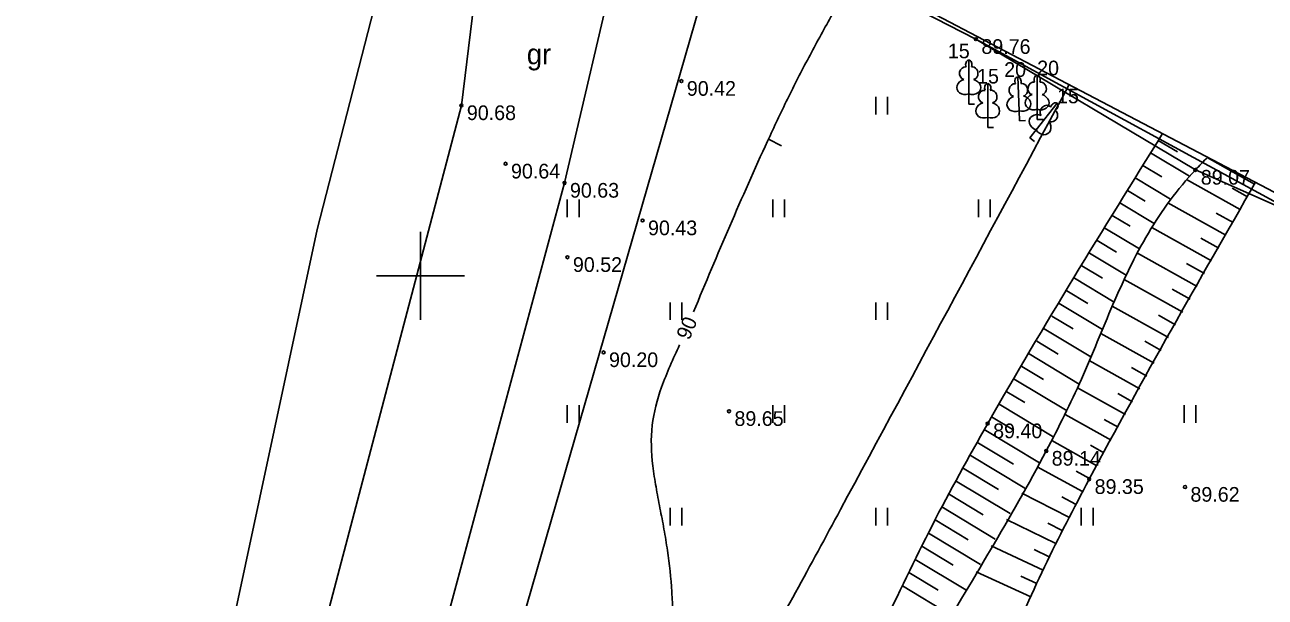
# Model space of a CAD drawing. Extents: x 635228 to 635525, y 248590 to 248800.
# Drawn here: x 635336.53 to 635378.76, y 248739.05 to 248758.56 of the extents above; entities that cross this region are included whole.
import ezdxf

# ---------------------------------------------------------------- set-up
doc = ezdxf.new("R2010")
doc.units = 0
for name, color, linetype in [('CELI_CMAL_####_####_#', 7, 'Continuous'), ('CELI_CSEG_####_TKST_#', 7, 'Continuous'), ('GEOD_ELEM_####_####_#', 7, 'Continuous'), ('NORB_ZOGS_ZSTP_####_#', 7, 'Continuous'), ('RAMI_UZMR_####_####_#', 7, 'Continuous'), ('RELJ_AATZ_####_TKST_#', 7, 'Continuous'), ('RELJ_ELEM_####_####_#', 7, 'Continuous'), ('RELJ_HORZ_####_TKST_#', 7, 'Continuous'), ('RELJ_HORZ_PAMT_####_#', 7, 'Continuous'), ('RELJ_HORZ_RESN_####_#', 7, 'Continuous'), ('RELJ_NOGA_####_####_#', 7, 'Continuous'), ('RELJ_NOGL_####_####_#', 7, 'Continuous'), ('ROBZ_IERR_####_####_#', 7, 'Continuous'), ('ROBZ_PROJ_####_####_#', 7, 'Continuous'), ('ROBZ_UZMR_####_####_#', 7, 'Continuous'), ('TERT_DIAM_####_TKST_#', 7, 'Continuous'), ('TERT_ELEM_####_####_#', 7, 'Continuous')]:
    doc.layers.add(name, color=color, linetype=linetype)

msp = doc.modelspace()

# ---------------------------------------------------------------- linework, layer by layer
at = {"layer": 'CELI_CMAL_####_####_#'}
for points in [[(635327.703, 248680.035), (635336.747, 248691.797), (635341.71, 248705.602), (635344.776, 248717.251), (635350.856, 248738.106), (635354.904, 248753.168), (635356.755, 248761.086), (635356.988, 248762.081)], [(635352.126, 248761.775), (635351.394, 248755.812), (635346.791, 248738.298), (635340.529, 248716.56), (635338.144, 248706.864), (635332.779, 248692.762), (635327.977, 248685.285), (635325.201, 248682.696)]]:
    msp.add_lwpolyline(points, dxfattribs=at)
at = {"layer": 'GEOD_ELEM_####_####_#'}
for p, q in [((635350, 248751.5), (635350, 248750)), ((635348.5, 248750), (635350, 248750)), ((635350, 248750), (635350, 248748.5)), ((635350, 248750), (635351.5, 248750))]:
    msp.add_line(p, q, dxfattribs=at)
at = {"layer": 'NORB_ZOGS_ZSTP_####_#'}
msp.add_lwpolyline([(635360.648, 248762.312), (635368.914, 248758.068), (635380.222, 248751.913), (635388.377, 248747.789), (635390.826, 248746.16), (635396.286, 248743.485), (635409.766, 248736.46), (635417.87, 248732.3), (635426.003, 248728.155), (635436.69, 248722.584), (635450.108, 248715.457), (635458.287, 248711.346), (635460.113, 248714.625)], dxfattribs=at)
at = {"layer": 'RAMI_UZMR_####_####_#'}
for points in [[(635352.126, 248761.775), (635360.648, 248762.312), (635368.914, 248758.068), (635376.384, 248753.612), (635380.222, 248751.913)], [(635379.918, 248627.738), (635364.657, 248634.365), (635359.326, 248636.387), (635355.893, 248639.014), (635323.971, 248655.917), (635326.8, 248663.851), (635331.354, 248676.262), (635327.703, 248680.035), (635326.374, 248681.182), (635325.201, 248682.696), (635327.977, 248685.285), (635332.779, 248692.762), (635338.144, 248706.864), (635340.529, 248716.56), (635346.791, 248738.298), (635351.394, 248755.812), (635352.126, 248761.775)]]:
    msp.add_lwpolyline(points, dxfattribs=at)
at = {"layer": 'RELJ_ELEM_####_####_#'}
for centre in [(635368.914, 248758.068), (635358.884, 248756.64), (635351.394, 248755.812), (635352.897, 248753.822), (635376.384, 248753.612), (635354.904, 248753.168), (635357.563, 248751.889), (635355.005, 248750.638), (635355.005, 248750.637), (635356.235, 248747.395), (635360.506, 248745.39), (635369.314, 248744.971), (635371.307, 248744.035), (635372.769, 248743.072), (635376.032, 248742.807)]:
    msp.add_circle(centre, 0.05, dxfattribs=at)
at = {"layer": 'RELJ_HORZ_PAMT_####_#'}
msp.add_spline([(635330.297, 248677.354), (635331.177, 248678.319), (635332.06, 248679.489), (635332.793, 248680.772), (635333.481, 248682.089), (635334.226, 248683.36), (635335.284, 248684.77), (635336.431, 248686.125), (635337.538, 248687.508), (635338.035, 248688.237), (635338.472, 248689.004), (635339.583, 248691.554), (635340.487, 248694.188), (635341.335, 248696.84), (635341.787, 248698.153), (635342.281, 248699.447), (635343.206, 248701.423), (635344.222, 248703.369), (635345.157, 248705.345), (635345.54, 248706.364), (635345.837, 248707.412), (635346.445, 248710.352), (635346.944, 248713.307), (635347.835, 248719.233), (635348.116, 248721.113), (635348.378, 248722.995), (635348.645, 248724.878), (635348.937, 248726.758), (635349.503, 248728.159), (635350.332, 248729.539), (635351.235, 248730.852), (635351.672, 248731.412), (635352.153, 248731.934), (635352.67, 248732.415), (635353.216, 248732.849), (635353.585, 248732.808), (635353.973, 248732.393), (635354.375, 248731.871), (635354.581, 248731.654), (635354.79, 248731.511), (635355.514, 248731.162), (635356.357, 248730.815), (635357.156, 248730.69), (635357.748, 248731.008), (635358.207, 248731.666), (635358.657, 248732.33), (635359.531, 248733.675), (635361.193, 248736.42), (635362.771, 248739.216), (635364.301, 248742.038), (635372.089, 248756.526)], degree=3, dxfattribs=at)
at = {"layer": 'RELJ_HORZ_RESN_####_#'}
msp.add_line((635361.849, 248754.663), (635362.292, 248754.431), dxfattribs=at)
for points in [[(635364.86, 248760.318), (635364.781, 248760.19), (635364.373, 248759.513), (635363.977, 248758.829), (635363.593, 248758.138), (635363.219, 248757.441), (635362.497, 248756.029), (635361.819, 248754.597), (635360.53, 248751.697), (635359.299, 248748.781)], [(635358.825, 248747.654), (635358.21, 248746.207), (635357.892, 248744.91), (635357.912, 248743.531), (635358.021, 248742.809), (635358.155, 248742.09), (635358.292, 248741.37), (635358.408, 248740.649), (635358.559, 248739.236), (635358.591, 248738.526), (635358.581, 248737.819), (635358.196, 248736.504), (635357.825, 248735.885), (635357.587, 248735.587), (635357.454, 248735.441), (635357.311, 248735.297), (635356.977, 248735.19), (635356.617, 248735.341), (635356.249, 248735.549), (635356.069, 248735.611), (635355.895, 248735.612), (635355.014, 248735.429), (635354.125, 248735.201), (635352.879, 248734.574), (635352.692, 248734.418), (635352.512, 248734.242), (635351.714, 248733.154), (635351.096, 248732.023), (635349.587, 248729.373), (635348.887, 248728.028), (635348.565, 248727.339), (635348.268, 248726.636), (635347.624, 248724.653), (635347.206, 248722.617), (635346.842, 248719.134)]]:
    msp.add_spline(points, degree=3, dxfattribs=at)
at = {"layer": 'RELJ_NOGA_####_####_#'}
for p, q in [((635375.123, 248754.619), (635375.774, 248754.228)), ((635374.86, 248754.194), (635376.183, 248753.397)), ((635378.399, 248753.133), (635376.791, 248754.033)), ((635374.598, 248753.768), (635375.241, 248753.381)), ((635374.337, 248753.342), (635375.543, 248752.615)), ((635377.911, 248752.26), (635376.082, 248753.284)), ((635374.076, 248752.915), (635374.679, 248752.552)), ((635378.155, 248752.696), (635377.638, 248752.986)), ((635373.816, 248752.488), (635374.982, 248751.786)), ((635377.423, 248751.387), (635375.452, 248752.49)), ((635373.556, 248752.061), (635374.165, 248751.694)), ((635377.667, 248751.824), (635377.094, 248752.144)), ((635373.297, 248751.633), (635374.483, 248750.919)), ((635376.934, 248750.515), (635374.9, 248751.653)), ((635373.039, 248751.205), (635373.699, 248750.808)), ((635377.179, 248750.951), (635376.575, 248751.289)), ((635372.781, 248750.777), (635374.032, 248750.023)), ((635376.446, 248749.642), (635374.41, 248750.781)), ((635372.523, 248750.349), (635373.227, 248749.925)), ((635376.69, 248750.078), (635376.078, 248750.421)), ((635372.265, 248749.92), (635373.615, 248749.107)), ((635375.958, 248748.769), (635373.966, 248749.884)), ((635372.008, 248749.491), (635372.723, 248749.061)), ((635376.202, 248749.206), (635375.596, 248749.545)), ((635371.752, 248749.062), (635373.219, 248748.179)), ((635375.469, 248747.897), (635373.555, 248748.968)), ((635371.495, 248748.633), (635372.219, 248748.197)), ((635375.713, 248748.333), (635375.127, 248748.662)), ((635371.239, 248748.203), (635372.829, 248747.246)), ((635374.981, 248747.024), (635373.162, 248748.042)), ((635370.983, 248747.774), (635371.715, 248747.333)), ((635375.225, 248747.46), (635374.665, 248747.774)), ((635370.727, 248747.344), (635372.432, 248746.318)), ((635370.471, 248746.915), (635371.211, 248746.469)), ((635374.492, 248746.152), (635372.773, 248747.114)), ((635374.737, 248746.588), (635374.206, 248746.885)), ((635370.215, 248746.485), (635372.016, 248745.401)), ((635369.96, 248746.055), (635370.58, 248745.682)), ((635374.004, 248745.279), (635372.376, 248746.19)), ((635374.248, 248745.715), (635373.747, 248745.996)), ((635369.704, 248745.626), (635371.566, 248744.504)), ((635369.448, 248745.196), (635370.203, 248744.741)), ((635373.516, 248744.406), (635371.957, 248745.278)), ((635373.76, 248744.843), (635373.283, 248745.109)), ((635369.193, 248744.766), (635371.076, 248743.633)), ((635368.942, 248744.334), (635370.187, 248743.584)), ((635373.027, 248743.534), (635371.503, 248744.387)), ((635373.272, 248743.97), (635372.811, 248744.228)), ((635368.695, 248743.899), (635370.576, 248742.766)), ((635368.453, 248743.461), (635369.676, 248742.724)), ((635372.542, 248742.659), (635370.998, 248743.497)), ((635372.783, 248743.097), (635372.326, 248743.353)), ((635368.215, 248743.02), (635370.075, 248741.9)), ((635367.98, 248742.578), (635369.164, 248741.865)), ((635372.075, 248741.775), (635370.478, 248742.597)), ((635367.749, 248742.134), (635369.573, 248741.036)), ((635372.306, 248742.219), (635371.836, 248742.468)), ((635367.521, 248741.688), (635368.653, 248741.006)), ((635371.629, 248740.88), (635369.957, 248741.697)), ((635367.295, 248741.24), (635369.07, 248740.171)), ((635371.85, 248741.329), (635371.359, 248741.572)), ((635371.198, 248739.978), (635369.436, 248740.801)), ((635367.071, 248740.791), (635368.14, 248740.147)), ((635371.412, 248740.43), (635370.897, 248740.676)), ((635366.849, 248740.341), (635368.566, 248739.307)), ((635366.629, 248739.89), (635367.628, 248739.288)), ((635370.778, 248739.07), (635368.923, 248739.919)), ((635370.987, 248739.525), (635370.444, 248739.774)), ((635366.41, 248739.438), (635368.062, 248738.443))]:
    msp.add_line(p, q, dxfattribs=at)
for points in [[(635375.27, 248754.857), (635369.314, 248744.971), (635367.429, 248741.507), (635365.696, 248737.957), (635363.943, 248734.417), (635363.006, 248732.681), (635362, 248730.984), (635361.355, 248730.103), (635360.628, 248729.283), (635359.885, 248728.474), (635359.193, 248727.625), (635357.58, 248725.368), (635356.018, 248723.079), (635353.089, 248718.349), (635349.569, 248710.638), (635349.163, 248709.221), (635348.864, 248707.772), (635348.539, 248706.335), (635348.053, 248704.954), (635343.12, 248694.162), (635337.407, 248681.667), (635331.093, 248670.147), (635326.8, 248663.851)], [(635326.8, 248663.851), (635325.31, 248661.345), (635325.174, 248660.918), (635325.219, 248660.451), (635325.416, 248659.984), (635325.736, 248659.553), (635326.126, 248659.27), (635326.575, 248659.146), (635327.409, 248659.333), (635327.907, 248659.688), (635328.397, 248660.078), (635328.864, 248660.506), (635329.288, 248660.978), (635331.594, 248663.918), (635332.687, 248665.412), (635333.734, 248666.95), (635337.875, 248673.353), (635341.554, 248680.001), (635347.428, 248693.006), (635353.063, 248706.101), (635354.098, 248708.621), (635355.097, 248711.155), (635356.117, 248713.682), (635356.653, 248714.935), (635357.216, 248716.179), (635358.916, 248719.218), (635360.822, 248722.14), (635362.339, 248724.363), (635363.916, 248726.545), (635365.467, 248728.744), (635366.906, 248731.015), (635368.464, 248733.981), (635369.863, 248737.03), (635371.249, 248740.086), (635372.769, 248743.072), (635378.435, 248753.196)]]:
    msp.add_spline(points, degree=3, dxfattribs=at)
at = {"layer": 'RELJ_NOGL_####_####_#'}
msp.add_spline([(635326.936, 248660.713), (635331.766, 248667.928), (635333.88, 248671.254), (635335.853, 248674.668), (635337.706, 248678.153), (635339.464, 248681.691), (635342.12, 248687.391), (635344.65, 248693.14), (635347.108, 248698.916), (635349.548, 248704.698), (635350.777, 248707.84), (635351.91, 248711.022), (635353.067, 248714.195), (635353.692, 248715.764), (635354.368, 248717.312), (635355.034, 248718.536), (635355.835, 248719.677), (635357.677, 248721.811), (635359.567, 248723.919), (635361.176, 248726.206), (635362.355, 248728.434), (635362.939, 248729.551), (635363.546, 248730.656), (635367.422, 248737.348), (635371.307, 248744.035), (635372.506, 248746.487), (635373.579, 248749.023), (635374.785, 248751.459), (635376.384, 248753.612), (635376.807, 248754.05)], degree=3, dxfattribs=at)
at = {"layer": 'ROBZ_IERR_####_####_#'}
msp.add_lwpolyline([(635390.87, 248797.676), (635383.387, 248769.687), (635386.484, 248768.447), (635478.377, 248731.658), (635482.561, 248729.828), (635465.459, 248707.539), (635458.607, 248711.134), (635360.483, 248762.615), (635360.888, 248769.918), (635363.321, 248797.676)], dxfattribs=at)
at = {"layer": 'ROBZ_PROJ_####_####_#'}
msp.add_lwpolyline([(635363.321, 248797.676), (635360.888, 248769.918), (635360.483, 248762.615), (635343.343, 248703.12), (635337.46, 248688.66), (635327.79, 248676.828), (635329.653, 248676.366), (635325.542, 248659.74), (635315.4, 248665.602), (635272.581, 248690.35), (635264.056, 248694.511), (635270.042, 248696.015), (635282.096, 248694.845), (635298.597, 248686.068), (635311.236, 248680.45), (635322.498, 248682.379), (635341.086, 248726.313), (635346.481, 248751.583), (635353.471, 248778.803), (635354.805, 248797.676)], dxfattribs=at)
at = {"layer": 'ROBZ_UZMR_####_####_#'}
msp.add_lwpolyline([(635325.542, 248659.74), (635329.653, 248676.366), (635327.79, 248676.828), (635337.46, 248688.66), (635343.343, 248703.12), (635360.483, 248762.615), (635458.607, 248711.134), (635465.459, 248707.539), (635439.457, 248681.038), (635424.543, 248670.014), (635420.979, 248667.379), (635407.07, 248653.18), (635400.067, 248641.149), (635395.162, 248617.539), (635389.031, 248621.062), (635375.858, 248629.115)], close=True, dxfattribs=at)
at = {"layer": 'TERT_ELEM_####_####_#'}
for p, q in [((635365.5, 248755.5), (635365.5, 248756.1)), ((635365.9, 248755.5), (635365.9, 248756.1)), ((635368.669, 248756.203), (635368.669, 248755.856)), ((635368.669, 248755.856), (635368.869, 248755.856)), ((635370.383, 248755.632), (635370.396, 248755.285)), ((635370.998, 248755.684), (635370.998, 248755.337)), ((635369.314, 248755.405), (635369.314, 248755.058)), ((635370.396, 248755.285), (635370.596, 248755.292)), ((635370.998, 248755.337), (635371.198, 248755.337)), ((635369.314, 248755.058), (635369.514, 248755.058)), ((635370.961, 248754.98), (635370.746, 248754.707)), ((635370.746, 248754.707), (635370.903, 248754.583)), ((635355, 248752), (635355, 248752.6)), ((635355.4, 248752), (635355.4, 248752.6)), ((635362, 248752), (635362, 248752.6)), ((635362.4, 248752), (635362.4, 248752.6)), ((635369, 248752), (635369, 248752.6)), ((635369.4, 248752), (635369.4, 248752.6)), ((635358.5, 248748.5), (635358.5, 248749.1)), ((635358.9, 248748.5), (635358.9, 248749.1)), ((635365.5, 248748.5), (635365.5, 248749.1)), ((635365.9, 248748.5), (635365.9, 248749.1)), ((635355, 248745), (635355, 248745.6)), ((635355.4, 248745), (635355.4, 248745.6)), ((635362, 248745), (635362, 248745.6)), ((635362.4, 248745), (635362.4, 248745.6)), ((635376, 248745), (635376, 248745.6)), ((635376.4, 248745), (635376.4, 248745.6)), ((635358.5, 248741.5), (635358.5, 248742.1)), ((635358.9, 248741.5), (635358.9, 248742.1)), ((635365.5, 248741.5), (635365.5, 248742.1)), ((635365.9, 248741.5), (635365.9, 248742.1)), ((635372.5, 248741.5), (635372.5, 248742.1)), ((635372.9, 248741.5), (635372.9, 248742.1))]:
    msp.add_line(p, q, dxfattribs=at)
for points in [[(635368.669, 248757.356), (635368.669, 248756.203)], [(635368.759, 248757.124), (635368.758, 248757.125)], [(635369.314, 248756.558), (635369.314, 248755.405)], [(635370.34, 248756.784), (635370.383, 248755.632)], [(635370.438, 248756.555), (635370.437, 248756.556)], [(635370.998, 248756.837), (635370.998, 248755.684)], [(635371.087, 248756.605), (635371.086, 248756.606)], [(635369.404, 248756.325), (635369.403, 248756.326)], [(635371.676, 248755.884), (635370.961, 248754.98)], [(635371.602, 248755.646), (635371.602, 248755.648)]]:
    msp.add_lwpolyline(points, dxfattribs=at)
for centre, major_axis, ratio, start_param, end_param in [((635368.669, 248757.207), (0, -0.15), 0.707107, 3.14537, 5.287485), ((635368.669, 248757.207), (0, -0.15), 0.707107, 0.995701, 3.137816), ((635368.541, 248756.912), (-0.039, -0.212), 0.861323, 3.141593, 6.283185), ((635368.797, 248756.912), (0.039, -0.212), 0.861323, 0, 3.141593), ((635368.579, 248756.449), (0.307, 0.095), 0.814445, 1.570796, 4.752015), ((635368.759, 248756.449), (-0.307, 0.095), 0.814445, 1.531171, 4.712389), ((635369.314, 248756.408), (0, -0.15), 0.707107, 3.14537, 5.287485), ((635369.314, 248756.408), (0, -0.15), 0.707107, 0.995701, 3.137816), ((635370.228, 248756.335), (-0.031, -0.214), 0.861323, 3.141593, 6.283185), ((635370.346, 248756.634), (0.006, -0.15), 0.707107, 3.14537, 5.287485), ((635370.345, 248756.634), (0.006, -0.15), 0.707107, 0.995701, 3.137816), ((635370.485, 248756.344), (0.047, -0.211), 0.861323, 0, 3.141593), ((635370.869, 248756.392), (-0.039, -0.212), 0.861323, 3.141593, 6.283185), ((635370.998, 248756.687), (0, -0.15), 0.707107, 3.14537, 5.287485), ((635370.997, 248756.687), (0, -0.15), 0.707107, 0.995701, 3.137816), ((635371.126, 248756.392), (0.039, -0.212), 0.861323, 0, 3.141593), ((635369.186, 248756.113), (-0.039, -0.212), 0.861323, 3.141593, 6.283185), ((635369.442, 248756.113), (0.039, -0.212), 0.861323, 0, 3.141593), ((635370.284, 248755.874), (0.303, 0.106), 0.814445, 1.570796, 4.752015), ((635370.463, 248755.881), (-0.31, 0.084), 0.814445, 1.531171, 4.712389), ((635370.908, 248755.93), (0.307, 0.095), 0.814445, 1.570796, 4.752015), ((635371.087, 248755.93), (-0.307, 0.095), 0.814445, 1.531171, 4.712389), ((635369.224, 248755.651), (0.307, 0.095), 0.814445, 1.570796, 4.752015), ((635369.404, 248755.651), (-0.307, 0.095), 0.814445, 1.531171, 4.712389), ((635371.299, 248755.615), (-0.162, -0.143), 0.861323, 3.141593, 6.283185), ((635371.501, 248755.456), (-0.101, -0.191), 0.861323, 0, 3.141593), ((635371.583, 248755.766), (-0.093, -0.118), 0.707107, 3.14537, 5.287485), ((635371.583, 248755.767), (-0.093, -0.118), 0.707107, 0.995701, 3.137816), ((635371.043, 248755.228), (0.3, -0.116), 0.814445, 1.570796, 4.752015), ((635371.184, 248755.117), (-0.182, 0.265), 0.814445, 1.531171, 4.712389)]:
    msp.add_ellipse(centre, major_axis=major_axis, ratio=ratio, start_param=start_param, end_param=end_param, dxfattribs=at)

# ---------------------------------------------------------------- texts
at = {"layer": 'CELI_CSEG_####_TKST_#'}
msp.add_text('gr', height=0.7, dxfattribs=at).set_placement((635353.621, 248757.21))
at = {"layer": 'RELJ_AATZ_####_TKST_#'}
for s, p in [(' 89.76', (635368.914, 248757.568)), (' 90.42', (635358.884, 248756.14)), (' 90.68', (635351.394, 248755.312)), (' 90.64', (635352.897, 248753.322)), (' 89.07', (635376.384, 248753.112)), (' 90.63', (635354.904, 248752.668)), (' 90.43', (635357.563, 248751.389)), (' 90.52', (635355.005, 248750.138)), (' 90.52', (635355.005, 248750.137)), (' 90.20', (635356.235, 248746.895)), (' 89.65', (635360.506, 248744.89)), (' 89.40', (635369.314, 248744.471)), (' 89.14', (635371.307, 248743.535)), (' 89.35', (635372.769, 248742.572)), (' 89.62', (635376.032, 248742.307))]:
    msp.add_text(s, height=0.5, dxfattribs=at).set_placement(p)
at = {"layer": 'RELJ_HORZ_####_TKST_#'}
msp.add_text('90', height=0.5, rotation=67.2323, dxfattribs=at).set_placement((635359.153, 248747.787))
at = {"layer": 'TERT_DIAM_####_TKST_#'}
for s, p in [('15', (635367.958, 248757.418)), ('20', (635369.876, 248756.784)), ('20', (635370.998, 248756.837)), ('15', (635368.952, 248756.558)), ('15', (635371.676, 248755.884))]:
    msp.add_text(s, height=0.5, dxfattribs=at).set_placement(p)

doc.saveas('drawing.dxf')
